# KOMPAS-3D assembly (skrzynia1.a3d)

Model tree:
1. X Axis
2. Y Axis
3. Z Axis
4. Origin
     Orientation = 1

Referenced files in C:\Work\01 К О М П А С\Модели примеры\2009_04_For_Poland_AXAPACK\My sample\Box_sample\: Base plate.a3d, Side plate.a3d, Front_plate.a3d, Top_plate.a3d
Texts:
  phr220400
  Three Point Plane
  Plane at Angle
  Line and Point Plane
  Axis through Two Vertices
  Axis of Feature
  Axis of Conical Surface
  Axis through Edge
  Trim by Surface
  Trim by Sketch
  Intersection Axis of Two Planes
  Two Line Plane
  Line and Face Plane
  Pattern by Sample
  Point in CM
  Feature with No History
  Linear Dimension from Line to Point
  Surface Finish Symbol
  Geometric Tolerance Symbol
  Leader #1
  Leader #2
  Leader #3
  Shape Deviations and Datum
  Node point number
  Mark of coordination axis
  Node point designation
  Mark/Reference designation with leader
  Mark/reference designation on line
  Mark/Reference designation without leader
